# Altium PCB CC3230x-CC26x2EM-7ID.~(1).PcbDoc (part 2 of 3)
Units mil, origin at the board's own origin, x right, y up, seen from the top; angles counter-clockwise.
Board outline 2700 x 2300 mil, 4 copper layers (Top Layer, GND, PWR, Bottom Layer), stack 48.84 mil thick; 159 components, 102 nets, 511 pads, 818 vias.
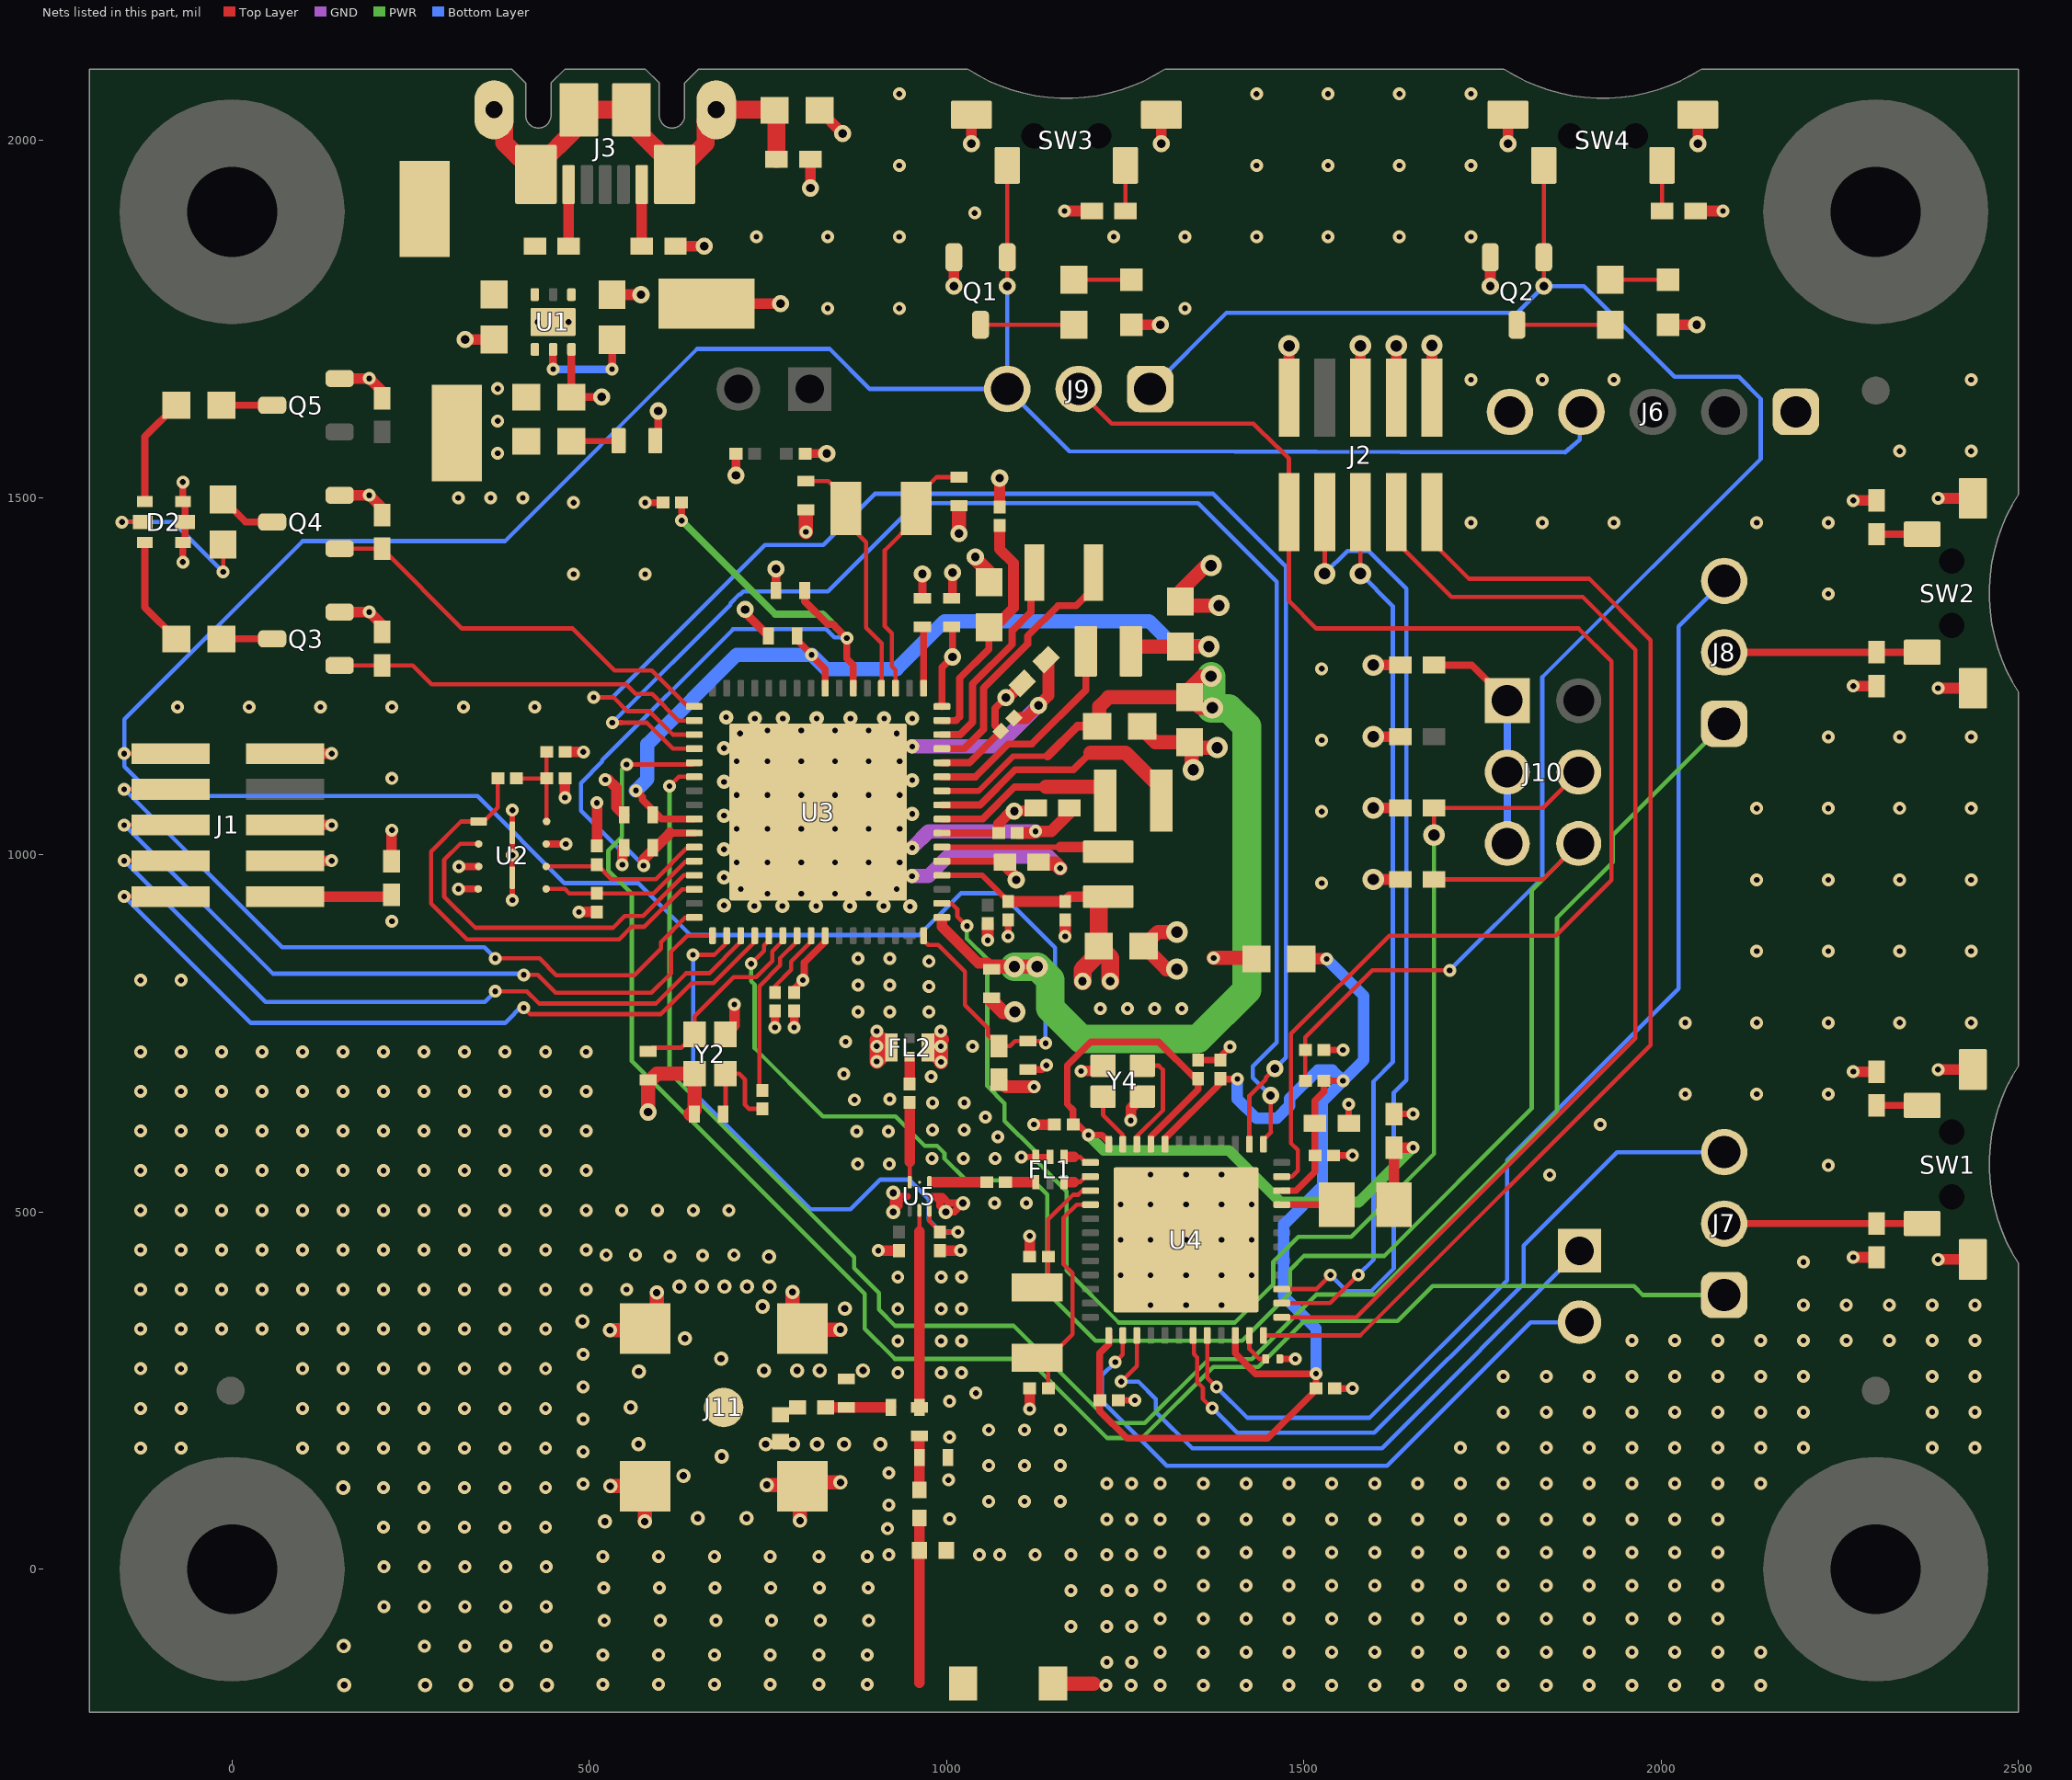
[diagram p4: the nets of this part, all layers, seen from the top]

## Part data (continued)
R14 R15: "RES, 100, 1%, 0.1 W, 0402", Alternate Manufacturer=YAGEO, Alternate PartNumber=RC0402FR-07100RL, Manufacturer=Panasonic, PartNumber=ERJ-2RKF1000X, Power_W=100mW, Supplier Part Number 1=P100LCT-ND, TempCo="100 ppm/C", Tolerance_%=1%, Value2=0.1W, Value_Code=100R, ValueDisplayed=100
R16 R17 R18: "RES, 100 k, 5%, 0.063 W, AEC-Q200 Grade 0, 0402", Alternate Manufacturer=YAGEO, Alternate PartNumber=RC0402JR-07100KL, Manufacturer=Vishay-Dale, PartNumber=CRCW0402100KJNED, Power_W=63mW, Supplier Part Number 1=541-100KJCT-ND, TempCo="200 ppm/C", Tolerance_%=5%, Value2=0.063W, Value_Code=100k
R19 R21 R27 R28: library part CMP-0027008-4, "RES, 0, 5%, 0.05 W, 0201", Manufacturer=Vishay-Dale, Power_W=50mW, Supplier Part Number 1=72M6743, TempCo=ppm/C, Tolerance_%=5%, Value2=0.05W, Value_Code=0000, ValueDisplayed=0
R20 R30 R31: library part CMP-0026823-3, "RES, 100 k, 5%, 0.063 W, AEC-Q200 Grade 0, 0402", Manufacturer=Vishay-Dale, Power_W=63mW, Supplier Part Number 1=541-100KJCT-ND, TempCo="200 ppm/C", Tolerance_%=5%, Value2=0.063W, Value_Code=100k
R29: library part CMP-0026886-3, "RES, 270, 5%, 0.063 W, AEC-Q200 Grade 0, 0402", Manufacturer=Vishay-Dale, Power_W=63mW, Supplier Part Number 1=541-270JCT-ND, TempCo="200 ppm/C", Tolerance_%=5%, Value2=0.063W, Value_Code=270R, ValueDisplayed=270
R32: library part CMP-0026892-5, "RES, 2.7 k, 5%, 0.063 W, AEC-Q200 Grade 0, 0402", Manufacturer=Vishay-Dale, Power_W=63mW, Supplier Part Number 1=541-2.7KJCT-ND, TempCo="200 ppm/C", Tolerance_%=5%, Value2=0.063W, Value_Code=2k70, ValueDisplayed=2.7k
R33 R34: library part CMP-0027011-3, "RES, 0, 5%, 0.05 W, 0201", Alternate Manufacturer=Vishay-Dale, Alternate PartNumber=CRCW02010000Z0ED, Manufacturer=Panasonic, Power_W=50mW, Supplier Part Number 1=P0.0AGCT-ND, TempCo="600 ppm/C", Tolerance_%=5%, Value2=0.05W, Value_Code=0000, ValueDisplayed=0
SH-J1 SH-J2 SH-J3 SH-J4: library part CMP-0003761-2, "Shunt, 2.54mm, Gold, Black", Manufacturer="Wurth Elektronik", Supplier Part Number 1=732-2678-ND
SW1 SW2 SW3 SW4: "Switch, SPST, 0.05 A, 12 VDC, SMD", Alternate Manufacturer=----, CurrentRating_mA=50A, Manufacturer=Diptronics, PartNumber=1188E-1K2-V-TR
TP1 TP2 TP3: library part CMP-0055152-1, "Test Point, Miniature, SMT", Manufacturer=Keystone, Supplier Part Number 1=36-5015TR-ND
U1: library part CMP-0073832-5, "Single Output LDO, 1A, Adj. (1.2 to 5.0V), Reverse Current Protection, DRV0006A (WSON-6)", Alternate Manufacturer="Texas Instruments", Alternate PartNumber=TPS73733DRVT, Operating Temperature Range="-40 to 125 C", Rating=Catalog
U2: library part CMP-0086651-1, "FLASH - NOR Memory IC 32Mb (4M x 8) SPI 80MHz 8-USON (4x3)", Manufacturer=Macronix
U3: library part CMP-0084310-2, "SimpleLink Wi-Fi, Single-Chip Wireless MCU Solution, RGK0064B (VQFN-64)", Alternate Manufacturer="Texas Instruments"
U4: library part CMP-0083675-2, "SimpleLink(TM) Bluetooth(R) 5 low energy Wireless MCU, RGZ0048A (VQFN-48)", Alternate Manufacturer="Texas Instruments", Alternate PartNumber=CC2642R1FRGZT, Operating Temperature Range="-40 to 85 C", Rating=#N/A
U5: library part CMP-0065464-1, "0.03 GHz-6 GHz SPDT Switch", Alternate Manufacturer=----, Manufacturer=Richwave
Y1: "CRYSTAL, 32.768KHz, 9PF, SMD", Alternate Manufacturer=----, Frequency Stability=+/-20ppm, Frequency_Fixed=32.768kHz, Manufacturer="Abracon Corporation", PartNumber=ABS07-32.768KHZ-9-T, Supplier Part Number 1=535-9544-1-ND
Y2: library part CMP-0077111-2, "Crystal, 40 MHz, 8 pF, SMD", Alternate Manufacturer=----, Alternate PartNumber="Order Directly from TXC", Frequency Stability=±15ppm, Frequency_Fixed=40MHz, Manufacturer="TXC Corporation"
Y3: library part CMP-0079303-1, "Crystal, 32.768 KHz, 20 ppm, 7 pF, SMD", Frequency Stability="20 ppm", Frequency_Fixed=32.768kHz, Load Capacitance="7 pF", Manufacturer=Epson, Supplier Part Number 1=732-FC135-32.76KAAG0
Y4: library part CMP-0088076-1, "48MHz ±20ppm Crystal 7pF 50 Ohms 4-SMD, No Lead", Frequency_Fixed=48MHz, Frequency Tolerance=20ppm, Load Capacitance=7pF, Manufacturer=Kyocera
ZZ1: library part CMP-0003616-3
ZZ2: library part CMP-0077236-1
ZZ3: library part CMP-0077237-1
ZZ4: library part CMP-0077238-1

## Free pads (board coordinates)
  rrect0% 16.73x16.73 smd paste-100 mask-100: 2(948.06,890.22)

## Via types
v1: diameter 18, hole 8, Top Layer to Bottom Layer, tented both sides, 626 vias
v2: diameter 19.68, hole 7.87, Top Layer to Bottom Layer, 55 vias
v3: diameter 20, hole 10, Top Layer to Bottom Layer, tented both sides, 48 vias
v4: diameter 24, hole 12, Top Layer to Bottom Layer, tented both sides, 37 vias
v5: diameter 20, hole 8, Top Layer to Bottom Layer, tented both sides, 24 vias
v6: diameter 30, hole 16, Top Layer to Bottom Layer, tented both sides, 23 vias
v7: diameter 20, hole 8, Top Layer to Bottom Layer, tented bottom, 4 vias
v8: diameter 18, hole 8, Top Layer to Bottom Layer, 1 vias

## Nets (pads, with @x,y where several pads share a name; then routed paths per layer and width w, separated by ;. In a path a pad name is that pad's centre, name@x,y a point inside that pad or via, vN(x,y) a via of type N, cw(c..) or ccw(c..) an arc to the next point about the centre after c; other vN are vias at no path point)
BT_P14_DIO_8: J5.2 U4.14 | length 892.8
  Top Layer w6: v1(1235.85,289.87) 1246.37,300.39 U4.14@1246.37,327.21
  Bottom Layer w6: v1(1235.85,289.87) 1217.27,271.29 1217.27,235.27 1307.69,144.85 1616.09,144.85 1816.99,345.75 J5.2@1885.45,345.75
BT_P15_DIO_9: J5.1 U4.15 | length 878.6
  Top Layer w6: v1(1244.22,262.62) 1266.05,284.45 U4.15@1266.05,327.21
  Bottom Layer w6: v1(1244.22,262.62) 1268.43,262.62 1292.66,238.39 1292.66,220.34 1343.71,169.3 1609,169.3 J5.1@1885.45,445.74
BT_P19_DIO_13: J7.3 U4.19 | length 1037.4
  Top Layer w6: U4.19@1344.79,327.21 1345.93,326.08 1345.93,301.04 1350.6,296.37 1350.6,262.19 1358.47,254.32 1358.47,238.31 1370.92,225.86 v1(1371.57,225.86)
  Bottom Layer w6: v1(1371.57,225.86) 1406.45,190.98 1598.26,190.98 1807.15,399.87 1807.15,452.87 1938.14,583.86 J7.3@2087.92,583.86
BT_P20_DIO_14: J8.3 U4.20 | length 1686.6
  Top Layer w6: U4.20@1364.48,327.21 1364.48,267.94 v1(1377.47,254.94)
  Bottom Layer w6: v1(1377.47,254.94) 1420.38,212.03 1591.64,212.03 1783.98,404.37 1783.98,572.56 2024.34,812.92 2024.34,1319.89 J8.3@2087.92,1383.47
BT_P35_nReset: J2.10 J9.2 U4.35 | length 2087.8
  Top Layer w6: J9.2@1182.22,1652.09 1230.67,1603.64 1429.21,1603.64 1461.5,1571.35 1462.23,1571.35 1478.92,1554.66 1478.92,1355.02 1517.13,1316.8 1884.18,1316.8 1930.14,1270.84 1930.14,964.73 1852.15,886.74 1619.21,886.74 1481.88,749.41 1481.88,596.22 1491.49,586.61 1491.49,558.18 1482.97,549.65 U4.35@1468.81,549.65
BT_RF: FL1.1 R34.2 | length 39.1
  Top Layer w15: R34.2@1082.14,541.78 FL1.1@1121.26,541.78
DCDC_SW: L7.1 U4.33 | length 77.1
  Top Layer w9.45: U4.33@1468.81,510.28 L7.1@1545.87,510.28
DIO_16/JTAG_TDO: J2.6 U4.26 | length 1220.6
  Top Layer w6: U4.26@1468.81,372.49 1536.5,372.49 v1(1575.87,411.86) ; v6(1578.92,1393.54) J2.6@1578.92,1470.38
  Bottom Layer w6: v1(1575.87,411.86) 1597.19,433.18 1597.19,682.87 1624.17,709.85 1624.17,1348.29 v6(1578.92,1393.54)
DIO_17/JTAG_TDI: J2.8 U4.27 | length 1372.8
  Top Layer w6: U4.27@1468.81,392.17 1517.34,392.17 v1(1537.03,411.86) ; v6(1528.92,1393.54) J2.8@1528.92,1470.38
  Bottom Layer w6: v6(1528.92,1393.54) 1560.77,1425.39 1590.6,1425.39 1643.24,1372.75 1643.24,684.82 1625.58,667.15 1625.58,421.19 1593.32,388.93 1559.95,388.93 v1(1537.03,411.86)
GND: C1.2 C2.2 C3.2 C4.2 C5.2 C6.2 C7.2 C8.2 C9.2 C10.2 C11.2 C12.2 C13.2 C14.2 C15.2 C16.2 C17.2 C18.2 C19.2 C20.2 C21.2 C22.2 C23.2 C24.2 C25.2 C26.2 C27.2 C28.2 C29.2 C30.2 C31.2 C32.2 C33.2 C34.2 C35.2 C36.2 C37.2 C38.2 C39.2 C40.2 C41.2 C42.2 C43.2 C44.1 C47.2 C49.2 C50.2 D1.2 E1.1 E1.2 FL1.5 FL1.6 FL2.2 FL2.4 J1.3 J1.5 J1.9 J2.3 J2.5 J2.9 J6.5 J11.2 J11.3 J11.4 J11.5 L2.2 L9.2 L10.1 L10.2 Q1.2 Q2.2 Q3.2 Q4.2 Q5.2 R3.1 R12.2 R13.2 R14.1 R15.1 R16.2 R17.2 R18.2 R23.1 R24.1 R30.1 R31.1 R32.1 R35.1 R36.1 SW1.1 SW1.2 SW2.1 SW2.2 SW3.1 SW3.2 SW4.1 SW4.2 TP3.1 U1.3 U1.7@449.17,1745.82 U2.4 U2.9 U2.10 U3.65@820,1060 U4.49 U5.2 Y2.2 Y2.4 Y4.2 Y4.4 | length 5704.5
  Top Layer w7.87: v1(392.2,936.49) U2.10@392.2,967.99 v1(392.2,999.49) U2.9@392.2,1030.98 v1(392.2,1062.48)
  Top Layer w9: v1(1104.36,577.21) FL1.6@1124.79,577.21 FL1.5@1144.47,577.21
  Top Layer w9.45: C6.2@1113.53,699.34 1133.51,699.34 v1(1139.5,705.33) ; C34.2@1240.12,236.52 v1(1263.22,236.52) ; C40.2@1351.65,712.65 C36.2@1383.14,712.65 1383.14,717.91 v1(1396.55,731.32) ; C44.1@1466.05,294.44 v1(1487.88,294.44) ; C5.2@1527.86,726.94 v1(1554.53,726.94) ; C38.2@1541.24,579.25 v1(1567.91,579.25) ; C35.2@1542.81,253.06 v1(1567.91,253.06) ; C37.2@1562.5,624.2 v1(1562.5,650.88) ; C39.2@1625.87,637.37 v1(1652.54,637.37)
  Top Layer w10: v1(316.8,952.24) U2.4@344.35,952.24 ; U3.65@820,1060 U3.65@860.07,1060 ; 945.03,521.77 939.86,521.77 ; 978.66,521.77 983.84,521.77 ; v1(1085.88,885.78) C19.2@1085.88,908.75 ; 939.86,521.77 933.32,515.22 933.32,508.45 v3(924.96,500.09) v3(924.96,526.81) 930.01,521.77 939.86,521.77 ; 983.84,521.77 990.38,515.22 990.38,508.45 v3(998.73,500.09) 1010.31,500.09 v3(1022.63,512.42) 1003.03,512.42 993.69,521.77 983.84,521.77
  Top Layer w11: U1.3@474.76,1707.43 C2.2@474.76,1640.84 v4(517.33,1640.84) ; D1.2@596.24,1578.75 v4(596.24,1621.32)
  Top Layer w12: v4(717.72,1343.4) 717.72,1339.08 C25.2@750.4,1306.4 ; v1(759.69,758.27) C28.2@759.69,781.27 ; C12.2@761.16,1369.99 v4(761.16,1400.37) ; v1(786.58,758.27) C18.2@786.58,781.27 ; C27.2@966,1362.62 v4(966,1393) ; C16.2@1007,1362.62 1008,1363.62 v4(1008,1395)
  Top Layer w15: 961.85,-158.86 L10.1@961.85,26.39 C49.2@961.85,71.71
  Top Layer w15.01: J1.3@76.64,991.65 v1(139.4,991.65) ; J1.5@76.64,1041.65 v1(139.4,1041.65) ; J1.9@76.64,1141.65 v1(139.4,1141.65) ; Q3.2@150.53,1339.78 v1(192.02,1339.78) 209.96,1321.84 R16.2@209.96,1312.22 ; Q4.2@150.53,1503.24 v1(192.02,1503.24) 209.96,1485.3 R17.2@209.96,1475.68 ; Q5.2@150.53,1666.7 v1(192.02,1666.7) 209.96,1648.77 R18.2@209.96,1639.14 ; v4(326.15,1721.21) C1.2@366.53,1721.21 ; v1(465.71,1080.03) 465.71,1106.71 C14.2@466.02,1107.03 ; v1(485.12,920.02) R24.1@510.53,920.02 ; R23.1@510.53,1012.27 v1(510.53,1072.76) ; v1(522.24,1105.16) 526.39,1105.16 537.67,1093.87 537.67,1066.95 C24.2@548.62,1056 ; C3.2@531.79,1784.02 v4(572.17,1784.02) ; v1(545.98,986.3) 545.98,1007.35 C13.2@548.62,1010 ; L2.2@620.43,1851.8 v4(660.81,1851.8) ; TP3.1@663.85,1771.57 v4(767.47,1771.57) ; Y2.4@690.51,748.7 702.91,761.1 v1(702.91,790.38) ; v4(809.12,1933.42) C4.2@809.12,1973.8 ; R3.1@821.99,2042.15 v4(854.35,2009.79) ; v1(904.21,446) R35.1@933.07,446 ; R36.1@990.63,446 v1(1019.49,446) ; v4(1009.88,1796.05) Q1.2@1009.88,1836.43 ; v4(1034.48,1995.5) SW3.2@1034.48,2035.88 ; v1(1116.13,224.42) C42.2@1116.13,253.28 ; C43.2@1116.13,437.63 v1(1116.13,466.49) ; v1(1121.98,622.46) C41.2@1150.84,622.46 ; v1(1164.76,1901.11) R14.1@1202.79,1901.11 ; v1(1188.01,697.41) 1210.99,697.41 Y4.4@1218.79,705.21 ; v1(1257.6,628.19) 1257.6,645.32 Y4.2@1273.91,661.63 ; v4(1300.23,1995.5) SW3.1@1300.23,2035.88 ; J2.9@1478.92,1635.73 v6(1478.92,1712.57) ; J2.5@1578.92,1635.73 v6(1578.92,1712.57) ; v6(1596.89,965.54) R32.1@1634.7,965.54 ; v6(1596.89,1065.54) R31.1@1634.7,1065.54 ; v6(1596.89,1165.54) R30.1@1634.7,1165.54 ; J2.3@1628.92,1635.73 v6(1628.92,1712.57) ; v4(1760.67,1796.05) Q2.2@1760.67,1836.43 ; v4(1785.27,1995.5) SW4.2@1785.27,2035.88 ; R15.1@2048.07,1901.11 v1(2086.1,1901.11) ; v4(2051.02,1995.5) SW4.1@2051.02,2035.88 ; v1(2268.67,436.62) R12.2@2301.1,436.62 ; v1(2268.67,1236.22) R13.2@2301.1,1236.22 ; v1(2387.18,433.66) SW1.1@2435.87,433.66 ; v1(2387.18,699.41) SW1.2@2435.87,699.41 ; v1(2387.18,1233.27) SW2.1@2435.87,1233.27 ; v1(2387.18,1499.02) SW2.2@2435.87,1499.02
  Top Layer w16.54: v1(1057.24,880.39) C32.2@1057.24,903.75 ; C11.2@1094.06,1191.37 1110.61,1191.37 v4(1128.37,1209.13) 1142.19,1222.96 1142.19,1270.24 C10.2@1139.03,1273.41 ; C9.2@1098.78,1030.47 1121.97,1030.47 v1(1124.35,1032.86) 1146.24,1032.86 1171.54,1058.15 C8.2@1171.54,1065.69 ; v1(1165.68,885.78) C17.2@1165.68,908.75
  Top Layer w17.72: 911.35,719.33 FL2.4@922.48,730.46 911.35,741.59 ; 984.79,719.33 FL2.2@973.66,730.46 984.79,741.59
  Top Layer w19.9: v4(582.17,639.98) 582.17,681.38 594.37,693.58 Y2.2@647.2,693.58 ; C31.2@641.38,637 647.2,642.83 Y2.2@647.2,693.58 ; Y2.2@646.89,693.27 Y2.2@647.2,693.58 ; v1(802.97,1451.95) C29.2@802.97,1479.33 ; v4(1016.97,1449.62) C30.2@1016.97,1485 ; v4(1040,1417) 1040,1414.43 1059,1395.43 C26.2@1059,1381.5 ; C7.2@1128.62,989.5 1130.29,987.83 1152.22,987.83 v1(1158.78,981.27) ; E1.2@1148.7,-160 1205.9,-160 ; v6(1322,840) 1307.5,840 C15.2@1275.5,872 1295.5,892 v6(1322,892) ; C21.2@1343,1154.5 1343,1121 v6(1345,1119) ; v6(1370,1405) 1363,1405 1327,1369 C23.2@1327,1354.5 1332.5,1349 v6(1381,1349)
  Top Layer w20: v3(528.72,334.74) 575.81,334.74 594.13,353.06 594.08,353.11 v3(594.08,387.25) ; v3(529.14,116.34) 575.59,116.34 576.55,117.3 J11.3@577.7,116.16 577.25,115.71 577.38,115.59 v3(577.38,66.73) ; v3(748.01,117.96) 796.36,117.96 J11.4@798.17,116.16 ; v3(784.08,387.98) 784.08,351.26 783.81,350.99 J11.5@798.17,336.63 799.62,335.18 799.97,335.53 v3(851.02,335.53) ; v3(794.63,67.96) 794.63,112.62 J11.4@798.17,116.16 ; J11.4@803.84,121.59 803.72,121.71 J11.4@798.17,116.16 ; J11.4@807.37,121.45 v3(851.33,121.45) ; v1@901.95,740.68 v1(901.95,732.2) ; 911.35,719.33 902.72,710.7 v1(901.95,710.7) v1(901.95,732.2) ; 911.35,741.59 v1(901.95,732.2) ; 984.79,719.33 v1@992.03,712.09 ; 984.79,741.59 993.28,741.59 990.38,738.7 992.03,737.05 v1@992.03,712.09 ; v1(992.03,710.11) v1@992.03,712.09 ; C22.2@1062.64,796.17 1078.6,780.21 v6(1095.31,780.21) ; C20.2@1273.5,1180 1273.5,1176 1291.99,1157.5 C21.2@1334,1157.5 ; v6(1378.43,1150.19) 1347.31,1150.19 1343,1154.5 C21.2@1342.5,1155 ; C21.2@1334,1157.5 1337.5,1154 1338.5,1155 C21.2@1342.5,1155 ; C21.2@1334,1157.5 C21.2@1340,1157.5 C21.2@1342.5,1155
  GND w19.9: v5(951.49,970.12) 974.12,970.12 1001.6,997.6 1142.45,997.6 v1(1158.78,981.27) ; v5(951.7,1009.9) 974.66,1032.86 v1(1124.35,1032.86) ; v5(951.7,1151.63) 1070.87,1151.63 v4(1128.37,1209.13)
  other v1: 1222.89,-162.35 1257.89,-162.35 1298.9,-162.35 1358.9,-162.35 1418.9,-162.35 1478.9,-162.35 1538.9,-162.35 1598.9,-162.35 1658.9,-162.35 1718.9,-162.35 1778.9,-162.35 1838.9,-162.35 1898.9,-162.35 1958.9,-162.35 2018.9,-162.35 2078.9,-162.35 2138.9,-162.35 518.9,-161 596.9,-161 674.9,-161 752.9,-161 820.9,-161 888.9,-161 1223.9,-130 1258.9,-130 518.9,-120 596.9,-120 674.9,-120 752.9,-120 820.9,-120 888.9,-120 1298.9,-115.88 1358.9,-115.88 1418.9,-115.88 1478.9,-115.88 1538.9,-115.88 1598.9,-115.88 1658.9,-115.88 1718.9,-115.88 1778.9,-115.88 1838.9,-115.88 1898.9,-115.88 1958.9,-115.88 2018.9,-115.88 2078.9,-115.88 2138.9,-115.88 269.31,-107.63 325.99,-107.63 382.67,-107.63 439.36,-107.63 1173.9,-80 1223.9,-80 1258.9,-80 520.9,-72 598.9,-72 676.9,-72 754.9,-72 822.9,-72 890.9,-72 1298.9,-69.41 1358.9,-69.41 1418.9,-69.41 1478.9,-69.41 1538.9,-69.41 1598.9,-69.41 1658.9,-69.41 1718.9,-69.41 1778.9,-69.41 1838.9,-69.41 1898.9,-69.41 1958.9,-69.41 2018.9,-69.41 2078.9,-69.41 212.62,-52.16 269.31,-52.16 325.99,-52.16 382.67,-52.16 439.36,-52.16 1173.9,-30 1223.9,-30 1258.9,-30 519.9,-26 597.9,-26 675.9,-26 753.9,-26 821.9,-26 889.9,-26 1298.9,-22.94 1358.9,-22.94 1418.9,-22.94 1478.9,-22.94 1538.9,-22.94 1598.9,-22.94 1658.9,-22.94 1718.9,-22.94 1778.9,-22.94 1838.9,-22.94 1898.9,-22.94 1958.9,-22.94 2018.9,-22.94 2078.9,-22.94 212.62,3.31 269.31,3.31 325.99,3.31 382.67,3.31 439.36,3.31 518.9,18 596.9,18 674.9,18 752.9,18 820.9,18 888.9,18 918.9,20 1045.9,20 1073.9,20 1123.9,20 1173.9,20 1223.9,20 1258.9,20 1298.9,23.53 1358.9,23.53 1418.9,23.53 1478.9,23.53 1538.9,23.53 1598.9,23.53 1658.9,23.53 1718.9,23.53 1778.9,23.53 1838.9,23.53 1898.9,23.53 1958.9,23.53 2018.9,23.53 2078.9,23.53 917.28,56.67 211.9,58.77 268.58,58.77 325.27,58.77 381.95,58.77 438.63,58.77 1223.9,70 1258.9,70 1298.9,70 1358.9,70 1418.9,70 1478.9,70 1538.9,70 1598.9,70 1658.9,70 1718.9,70 1778.9,70 1838.9,70 1898.9,70 1958.9,70 2018.9,70 2078.9,70 1004.22,70.54 918.9,90 1058.9,95 1108.9,95 1158.9,95 211.9,114.24 268.58,114.24 325.27,114.24 381.95,114.24 438.63,114.24 491.34,119.39 1223.9,120 1258.9,120 1298.9,120 1358.9,120 1418.9,120 1478.9,120 1538.9,120 1598.9,120 1658.9,120 1718.9,120 1778.9,120 1838.9,120 1898.9,120 1958.9,120 2018.9,120 2078.9,120 2138.9,120 1002.36,124.95 918.9,135 1058.9,145 1108.9,145 1158.9,145 491.34,164.74 -128.2,169.71 -71.52,169.71 98.53,169.71 155.22,169.71 211.9,169.71 268.58,169.71 325.27,169.71 381.95,169.71 438.63,169.71 1718.9,170 1778.9,170 1838.9,170 1898.9,170 1958.9,170 2018.9,170 2078.9,170 2138.9,170 2198.9,170 2378.9,170 2438.9,170 1003.9,185 1058.9,195 1108.9,195 1158.9,195 491.34,210.08 1778.9,220 1838.9,220 1898.9,220 1958.9,220 2018.9,220 2078.9,220 2138.9,220 2198.9,220 2378.9,220 2438.9,220 -128.2,225.17 -71.52,225.17 98.53,225.17 155.22,225.17 211.9,225.17 268.58,225.17 325.27,225.17 381.95,225.17 438.63,225.17 1003.9,235 1040.82,246.51 491.34,255.43 1778.9,270 1838.9,270 1898.9,270 1958.9,270 2018.9,270 2078.9,270 2138.9,270 2198.9,270 2378.9,270 2438.9,270 931.53,274.95 992.08,274.95 1020.76,274.95 -128.2,280.64 -71.52,280.64 98.53,280.64 155.22,280.64 211.9,280.64 268.58,280.64 325.27,280.64 381.95,280.64 438.63,280.64 491.34,300.78 931.53,319.6 992.08,319.6 1020.76,319.6 1958.9,320 2018.9,320 2078.9,320 2138.9,320 2198.9,320 2258.9,320 2318.9,320 2378.9,320 2438.9,320 -128.2,336.11 -71.52,336.11 -14.83,336.11 41.85,336.11 98.53,336.11 155.22,336.11 211.9,336.11 268.58,336.11 325.27,336.11 381.95,336.11 438.63,336.11 931.53,364.26 992.08,364.26 1020.76,364.26 2198.9,370 2258.9,370 2318.9,370 2378.9,370 2438.9,370 -128.2,391.57 -71.52,391.57 -14.83,391.57 41.85,391.57 98.53,391.57 155.22,391.57 211.9,391.57 268.58,391.57 325.27,391.57 381.95,391.57 438.63,391.57 495.32,391.57 552,391.57 931.53,408.91 992.08,408.91 1020.76,408.91 2198.9,430 612.44,438.06 658.44,439.06 523.44,440.06 564.44,440.06 702.44,440.06 -128.2,447.04 -71.52,447.04 -14.83,447.04 41.85,447.04 98.53,447.04 155.22,447.04 211.9,447.04 268.58,447.04 325.27,447.04 381.95,447.04 438.63,447.04 495.32,447.04 -128.2,502.51 -71.52,502.51 -14.83,502.51 41.85,502.51 98.53,502.51 155.22,502.51 211.9,502.51 268.58,502.51 325.27,502.51 381.95,502.51 438.63,502.51 495.32,502.51 545.32,502.51 595.32,502.51 645.32,502.51 695.32,502.51 1066.93,512.42 1111.23,512.42 1843.96,552 -128.2,557.98 -71.52,557.98 -14.83,557.98 41.85,557.98 98.53,557.98 155.22,557.98 211.9,557.98 268.58,557.98 325.27,557.98 381.95,557.98 438.63,557.97 495.32,557.97 2233.55,565.06 875.52,566.95 919.82,566.95 979.25,575.25 1023.54,575.25 1067.84,575.25 1071.33,605.31 -128.2,613.44 -71.52,613.44 -14.83,613.44 41.85,613.44 98.53,613.44 155.22,613.44 211.9,613.44 268.58,613.44 325.27,613.44 381.95,613.44 438.63,613.44 495.32,613.44 873.98,612.77 918.28,612.77 979.94,615.16 1024.23,615.16 1914.67,622.71 1054.22,632.74 980.29,653.04 1024.58,653.04 871.04,657.01 920.25,658.07 2033.55,665.06 2133.55,665.06 2233.55,665.06 -128.2,668.91 -71.52,668.91 -14.83,668.91 41.85,668.91 98.53,668.91 155.22,668.91 211.9,668.91 268.58,668.91 325.27,668.91 381.95,668.91 438.63,668.91 495.32,668.91 978.34,689.49 855.82,693.19 -128.2,724.38 -71.52,724.38 -14.83,724.38 41.85,724.38 98.53,724.38 155.22,724.38 211.9,724.38 268.58,724.38 325.27,724.38 381.95,724.38 438.63,724.38 495.32,724.38 991.79,732.07 1036.09,732.07 858.47,738.41 901.95,753.09 991.64,753.38 2033.55,765.06 2133.55,765.06 2233.55,765.06 2333.55,765.06 2433.55,765.06 875.93,780.27 920.23,780.27 975.27,780.4 1215.13,784.78 1253,784.78 1290.87,784.78 1328.73,784.78 975.27,815.62 875.93,817.53 920.23,817.53 -128.2,824.38 -71.52,824.38 975.27,850.84 875.93,854.78 920.23,854.78 2133.55,865.06 2233.55,865.06 2333.55,865.06 2433.55,865.06 223.69,906.85 1524.79,960.5 2133.55,965.06 2233.55,965.06 2333.55,965.06 2433.55,965.06 1524.79,1060.5 2133.55,1065.06 2233.55,1065.06 2333.55,1065.06 2433.55,1065.06 223.69,1106.85 1524.79,1160.5 2233.55,1165.06 2333.55,1165.06 2433.55,1165.06 -76.31,1206.85 23.69,1206.85 123.69,1206.85 223.69,1206.85 323.69,1206.85 423.69,1206.85 1524.79,1260.5 2233.55,1365.06 477.87,1392.99 577.87,1392.99 1733.55,1465.06 1833.55,1465.06 1933.55,1465.06 2133.55,1465.06 2233.55,1465.06 477.87,1492.99 2333.55,1565.06 2433.55,1565.06 1733.55,1665.06 1833.55,1665.06 1933.55,1665.06 2433.55,1665.06 833.55,1765.06 933.55,1765.06 1333.55,1765.06 733.55,1865.06 833.55,1865.06 933.55,1865.06 1233.55,1865.06 1333.55,1865.06 1433.55,1865.06 1533.55,1865.06 1633.55,1865.06 1733.55,1865.06 1039.08,1898.33 933.55,1965.06 1433.55,1965.06 1533.55,1965.06 1633.55,1965.06 1733.55,1965.06 933.55,2065.06 1433.55,2065.06 1533.55,2065.06 1633.55,2065.06 1733.75,2065.34
  other v2: 1285.34,369.53 1334.95,369.53 1384.56,369.53 1243.41,411.46 1285.34,411.46 1334.95,411.46 1384.56,411.46 1426.48,411.46 1243.41,461.07 1285.34,461.07 1334.95,461.07 1384.56,461.07 1426.48,461.07 1243.41,510.67 1285.34,510.67 1334.95,510.67 1384.56,510.67 1426.48,510.67 1285.34,552.6 1334.95,552.6 1384.56,552.6 749.13,945.83 796.38,945.83 843.62,945.83 890.87,945.83 705.83,989.13 749.13,989.13 796.38,989.13 843.62,989.13 890.87,989.13 934.17,989.13 705.83,1036.38 749.13,1036.38 796.38,1036.38 843.62,1036.38 890.87,1036.38 934.17,1036.38 705.83,1083.62 749.13,1083.62 796.38,1083.62 843.62,1083.62 890.87,1083.62 934.17,1083.62 705.83,1130.87 749.13,1130.87 796.38,1130.87 843.62,1130.87 890.87,1130.87 934.17,1130.87 749.13,1174.17 796.38,1174.17 843.62,1174.17 890.87,1174.17 427.51,1745.82 470.82,1745.82
  other v3: 156.94,-162.1 270.31,-162.1 326.99,-162.1 383.67,-162.1 440.36,-162.1 155.94,-107.63 521.64,66.73 651.61,71.66 719.89,71.66 155.22,114.24 631.41,130.9 685.23,158 568.55,174.93 746.6,175 784.51,175 818.61,175 856.46,175 907.13,175 557.73,226.7 568.98,276.85 744.16,278.29 790.71,278.29 822.42,278.29 882.9,278.29 684.24,294.62 633.56,323.19 490.34,347.12 857.25,364.75 742.11,367.78 625.74,395.54 657.35,395.54 688.97,395.54 720.58,395.54 752.2,395.54 751.18,437.32
  other v5: 730.66,928.3 769.9,928.3 817.14,928.3 864.39,928.3 911.63,928.3 948.67,927.77 688.3,929.12 688.3,968.37 688.3,1007.61 688.3,1054.86 951.7,1057.14 688.3,1102.1 951.7,1104.39 688.3,1149.34 731.48,1190.88 770.72,1190.88 817.97,1190.88 865.21,1190.88 912.46,1190.88 951.7,1190.88 691.25,1192.67
  other v7: 711.89,951.89 929.9,951.89 710.9,1169.9 929.9,1169.9
NetC3_1: C3.1 U1.2 | length 151.8
  Top Layer w11: v1(449.17,1679.66) U1.2@449.17,1707.43 ; v1(531.79,1679.66) C3.1@531.79,1721.03
  Bottom Layer w11: v1(449.17,1679.66) v1(531.79,1679.66)
NetC4_1: C4.1 J3.6 J3.7 J3.8 J3.9 J3.10 J3.11 R3.2 | length 685.6
  Top Layer w25: J3.10@366.49,2042.91 380.91,2028.5 380.91,1996.51 J3.11@425.05,1952.36 425.05,1960.63 485.09,2020.67 J3.9@485.09,2042.91 J3.8@558.91,2042.91 558.91,2022.34 618.95,1962.3 J3.6@618.95,1952.36 662.55,1995.96 662.55,2027.95 J3.7@677.51,2042.91 758.24,2042.91 R3.2@759,2042.15 761.88,2039.28 C4.1@761.88,1973.8
NetC5_1: C5.1 J9.1 Q2.1 R8.1 SW4.4 | length 2430.2
  Top Layer w6: R8.1@1501.88,683.63 C5.1@1501.88,726.94 1501.88,744.55 1595.64,838.32 v1(1703.73,838.32) ; v4(1835.47,1796.05) Q2.1@1835.47,1836.43 SW4.4@1835.47,1965.02
  Bottom Layer w6: J9.1@1284.68,1652.09 1391.34,1758.75 1798.17,1758.75 v4(1835.47,1796.05) 1891.61,1796.05 2018.51,1669.14 2108.29,1669.14 2138.99,1638.44 2138.99,1554.29 1833.38,1248.67 1833.38,967.97 v1(1703.73,838.32)
NetC12_1: C12.1 C13.1 R19.1 U3.10 U3.54 | length 1215
  Top Layer w10: 612.71,1030.47 U3.10@646.77,1030.47 ; v1(628.99,1467.85) R19.1@628.99,1492.99 ; C12.1@801.16,1369.99 801.16,1354.87 833.19,1322.84 840.59,1322.84 v1(860.22,1303.21) 860.22,1274.67 869.21,1265.68 U3.54@869.21,1233.23
  Top Layer w15.01: v1(575.81,984.99) 575.81,993.57 588.62,1006.38 C13.1@588.62,1010 592.24,1010 612.71,1030.47
  PWR w10: v1(628.99,1467.85) 759.84,1337 826.43,1337 v1(860.22,1303.21)
  Bottom Layer w6: v1(575.81,984.99) 555.24,1005.56 544.44,1005.56 488,1062.01 488,1100.55 517.99,1130.55 517.99,1132.3 700.71,1315.01 ; 700.71,1316.01 831,1316.01 842.78,1304.22 v1@859.21,1304.22
NetC14_1: C14.1 R21.1 R22.2 U2.8 | length 139.6
  Top Layer w6: R22.2@397.78,1107.03 C14.1@440.04,1107.03 ; U2.8@440.04,1046.73 C14.1@440.04,1107.03 ; R21.1@440.04,1144.04 C14.1@440.04,1107.03
NetC26_1: C26.1 R27.1 U3.47 | length 338.5
  Top Layer w10: U3.47@993.23,1187.95 1012.95,1187.95 1017.98,1192.98 1017.98,1246.98 1059,1288 C26.1@1059,1318.5
  Top Layer w15.01: C26.1@1059,1318.5 1066.5,1318.5 1093.35,1345.35 1093.35,1408.65 1074,1428 R27.1@1073.99,1461.03
NetC27_1: C27.1 U3.49 | length 86.5
  Top Layer w10: C27.1@966,1319 967.64,1317.36 U3.49@967.64,1233.23
NetC28_1: C28.1 U3.24 | length 91.9
  Top Layer w6: C28.1@759.69,807.25 759.69,816.24 782.42,838.97 782.42,850.52 U3.24@810.16,878.26
NetC29_1: C29.1 U3.52 Y1.2 | length 352.2
  Top Layer w6: C29.1@803,1522.95 834.47,1522.95 858.79,1498.64 Y1.2@858.79,1485 858.79,1466.21 887.3,1437.7 887.3,1388.32 887.3,1317.93 909,1296.22 909,1233.62 U3.52@908.58,1233.23
NetC30_1: C30.1 U3.51 Y1.1 | length 362.9
  Top Layer w6: U3.51@928.27,1233.23 928.27,1258.7 922.97,1264 922.97,1310.03 913.28,1319.73 913.28,1426.31 957.19,1470.21 957.19,1500.21 985.59,1528.62 C30.1@1016.97,1528.62
NetC31_1: C31.1 R28.1 Y2.3 | length 150.8
  Top Layer w6: C31.1@686.89,637 690.51,640.62 Y2.3@690.51,693.58 709.61,693.58 717.66,685.53 717.66,650.15 723.4,644.41 R28.1@742.12,644.41
NetC33_1: C33.1 U3.22 Y2.1 | length 282.3
  Top Layer w6: C33.1@582.17,725 587.17,730 628.5,730 Y2.1@647.2,748.7 647.2,774.13 702.06,828.99 733.14,828.99 755.76,851.61 755.76,864.97 770.79,880 U3.22@770.79,886.77
NetC42_1: C42.1 U4.4 Y3.1 | length 326
  Top Layer w6: C42.1@1142.11,253.28 1142.11,280.65 Y3.1@1126.51,296.24 1143.4,296.24 1176.03,328.88 1176.03,414.41 1163.52,426.93 1163.52,492.09 1181.7,510.28 U4.4@1201.09,510.28
NetC43_1: C43.1 U4.3 Y3.2 | length 177.1
  Top Layer w6: Y3.2@1126.51,394.67 1142.11,410.27 C43.1@1142.11,437.63 1142.11,489.59 1176.68,524.16 1184.05,524.16 1189.86,529.97 U4.3@1201.09,529.97
NetC44_2: C44.2 U4.23 | length 47.5
  Top Layer w6: U4.23@1423.53,327.21 1423.53,308.32 1437.41,294.44 C44.2@1446.37,294.44
NetC45_1: C45.1 C48.1 U5.5 | length 275.9
  Top Layer w6: 961.85,472.66 U5.5@961.85,502.41
  Top Layer w15: C48.1@961.85,226.53 961.85,472.66
NetC45_2: C45.2 C46.1 C47.1 | length 90.3
  Top Layer w15: C46.1@830.69,226.4 C45.2@920.83,226.4 ; C45.2@921.71,226.4 C45.2@921.85,226.53
NetC46_2: C46.2 J11.1 L9.1
NetC48_2: C48.2 C49.1 C50.1 | length 73.1
  Top Layer w15: C49.1@961.85,111.08 C50.1@961.85,156.39 C48.2@961.85,184.18
NetD1_1: D1.1 R2.2 | length 66.1
  Top Layer w9: R2.2@474.76,1578.75 D1.1@540.87,1579.57
NetD2_2: D2.2 R11.2 | length 153.1
  Top Layer w10: D2.2@-122.1,1494.38 -122.1,1585.33 R11.2@-78.13,1629.3
NetD2_4: D2.4 R10.2 | length 237.7
  Top Layer w6: v1(-154.04,1465.84) D2.4@-125.05,1465.84 ; v1(-12.58,1395.99) R10.2@-12.58,1434.34
  Bottom Layer w6: v1(-154.04,1465.84) -82.43,1465.84 v1(-12.58,1395.99)
NetD2_6: D2.6 R9.2 | length 153.1
  Top Layer w10: D2.6@-122.1,1437.29 -122.1,1346.35 R9.2@-78.13,1302.37
NetD3_1: D3.1 R6.2 | length 80.4
  Top Layer w6: R6.2@1177.99,1804.93 D3.1@1258.42,1804.93
NetD4_1: D4.1 R7.2 | length 80.4
  Top Layer w6: R7.2@1928.77,1804.93 D4.1@2009.21,1804.93
NetFL1_3: FL1.3 U4.2 | length 37.1
  Top Layer w6: 1177.81,541.78 1186.63,541.78 1194.5,549.65 U4.2@1201.09,549.65
  Top Layer w15: FL1.3@1167.27,541.78 1177.81,541.78
NetFL1_4: FL1.4 U4.1 | length 37.1
  Top Layer w6: 1177.81,577.21 1186.63,577.21 1194.5,569.34 U4.1@1201.09,569.34
  Top Layer w15: FL1.4@1167.27,577.21 1177.81,577.21
NetFL2_3: FL2.3 R33.2 | length 37.2
  Top Layer w15: R33.2@948.07,679.36 FL2.3@948.07,716.6
NetJ1_1: J1.1 R1.2 | length 145.7
  Top Layer w15.01: J1.1@76.64,941.65 R1.2@222.3,941.42
NetJ3_1: J3.1 L1.1 | length 86.4
  Top Layer w15.01: L1.1@470.82,1851.8 J3.1@470.82,1938.19
NetJ3_5: J3.5 L2.1 | length 86.4
  Top Layer w15.01: L2.1@573.18,1851.8 J3.5@573.18,1938.19
NetJ7_2: J7.2 R12.1 SW1.3 | length 490.3
  Top Layer w10: SW1.3@2365.01,483.86 R12.1@2301.1,483.86 ; R12.1@2301.1,483.86 J7.2@2087.92,483.86 R12.1@2301.1,483.86
NetJ8_2: J8.2 R13.1 SW2.3 | length 277.1
  Top Layer w10: J8.2@2087.92,1283.47 R13.1@2301.1,1283.47 SW2.3@2365.01,1283.47
NetJ10_1: J10.1 J10.3 J10.5 R29.1 | length 323
  Top Layer w10: R29.1@1681.95,1265.54 1734.61,1265.54 J10.1@1784.35,1215.81
  Bottom Layer w10: J10.5@1784.35,1015.81 J10.3@1784.35,1115.81 J10.1@1784.35,1215.81
NetL3_2: L3.2 U3.38 | length 235.4
  Top Layer w8: U3.38@993.23,1010.79 1159.41,1010.79
  Top Layer w15.01: 1159.41,1010.79 1219.58,1010.79 L3.2@1226,1004.37
NetL4_1: L4.1 U3.41 | length 374.9
  Top Layer w10: U3.41@993.23,1069.84 1046.62,1069.84 1095.78,1119 1176.99,1119 1200.99,1143
  Top Layer w20: 1200.99,1143 1250,1143 1300.37,1092.63 L4.1@1300.37,1076
NetL4_2: L4.2 U3.40 | length 268
  Top Layer w10: U3.40@993.23,1050.16 1050.29,1050.16 1095.13,1095 1138.8,1095
  Top Layer w20: 1138.8,1095 1216.63,1095 L4.2@1216.63,1081 ; L4.2@1216.63,1076 L4.2@1216.63,1081 ; L4.2@1221.63,1076 L4.2@1216.63,1081
NetL5_2: L5.2 U3.43 | length 306.1
  Top Layer w10: U3.43@993.23,1109.21 1040.21,1109.21 1086,1155 1119,1155 1194.63,1230.63 L5.2@1194.63,1285
NetL6_1: L6.1 U3.46 | length 295.3
  Top Layer w10: U3.46@993.23,1168.27 1018.72,1168.27 1036.08,1185.63 1036.08,1239.14 1091.6,1294.66 1091.6,1313.65 1117.66,1339.71 1117.66,1390 L6.1@1122.66,1395
NetL6_2: L6.2 U3.45 | length 367.4
  Top Layer w10: U3.45@993.23,1148.58 1024.49,1148.58 1051.53,1175.62 1051.53,1233.37 1113.19,1295.04 1113.19,1306.06 1155.96,1348.83 1181.21,1348.83 1205.34,1372.95 L6.2@1205.34,1395
NetQ1_3: Q1.3 R6.1 | length 130.7
  Top Layer w6: Q1.3@1047.28,1741.94 R6.1@1177.99,1741.94
NetQ2_3: Q2.3 R7.1 | length 130.7
  Top Layer w6: Q2.3@1798.07,1741.94 R7.1@1928.77,1741.94
NetQ3_3: Q3.3 R9.1 | length 71.2
  Top Layer w10: R9.1@-15.13,1302.37 Q3.3@56.05,1302.37
NetQ4_3: Q4.3 R10.1 | length 81.7
  Top Layer w10: R10.1@-12.58,1497.33 18.92,1465.84 Q4.3@56.05,1465.84
NetQ5_3: Q5.3 R11.1 | length 71.2
  Top Layer w10: R11.1@-15.13,1629.3 Q5.3@56.05,1629.3
NetR4_2: R4.2 SW1.4 | length 63.9
  Top Layer w10: R4.2@2301.1,649.22 SW1.4@2365.01,649.22
NetR5_2: R5.2 SW2.4 | length 63.9
  Top Layer w10: R5.2@2301.1,1448.82 SW2.4@2365.01,1448.82
NetR14_2: R14.2 SW3.3 | length 63.9
  Top Layer w6: R14.2@1250.03,1901.11 SW3.3@1250.03,1965.02
NetR15_2: R15.2 SW4.3 | length 63.9
  Top Layer w6: R15.2@2000.82,1901.11 SW4.3@2000.82,1965.02
NetR28_2: R28.2 U3.23 | length 240.1
  Top Layer w6: R28.2@742.12,670.39 737.7,674.82 737.7,816.17 766.98,845.45 766.98,855.52 790.46,879 U3.23@790.47,886.77
NetR33_1: R33.1 U5.3 | length 111.6
  Top Layer w6: U5.3@948.07,541.78 948.07,570.23
  Top Layer w15: 948.07,570.23 R33.1@948.07,653.38
NetR34_1: R34.1 U5.1 | length 75.8
  Top Layer w15: 980.37,541.78 R34.1@1056.16,541.78
NetU4_46: U4.46 Y4.3 | length 150.3
  Top Layer w6: U4.46@1266.05,594.93 1266.05,605.97 1302.5,642.42 1302.5,699.1 1296.67,704.93 Y4.3@1273.91,704.93
NetU4_47: U4.47 Y4.1 | length 78.1
  Top Layer w6: Y4.1@1218.79,661.63 1218.79,635.82 1246.37,608.25 U4.47@1246.37,594.93
P_24/JTAG_TMS: J2.2 U4.24 | length 1672.3
  Top Layer w6: U4.24@1443.22,327.21 1578.53,327.21 1984.94,733.62 1984.94,1300.71 1899.27,1386.38 1730.8,1386.38 1678.92,1438.26 J2.2@1678.92,1470.38
P_25/JTAG_TCK: J2.4 U4.25 | length 1630.1
  Top Layer w6: U4.25@1468.81,352.8 1573.17,352.8 1963.78,743.41 1963.78,1286.99 1889.98,1360.79 1706.17,1360.79 1628.92,1438.04 J2.4@1628.92,1470.38
SFL_CLK: R23.2 U2.6 U3.11 | length 235.4
  Top Layer w6: U2.6@439.44,983.74 507.98,983.74 R23.2@510.53,986.29 530.83,965.98 592.86,965.98 637.67,1010.79 U3.11@646.77,1010.79
SFL_CS: R22.1 U2.1 U3.14 | length 651.1
  Top Layer w6: R22.1@371.8,1107.03 371.8,1066.05 352.48,1046.73 U2.1@344.95,1046.73 320.57,1046.73 278.31,1004.47 278.31,931.68 328.5,881.5 541.4,881.5 559.25,899.35 577.15,899.35 629.53,951.73 U3.14@646.77,951.73
SFL_DIN: U2.2 U3.13 | length 507.3
  Top Layer w6: U2.2@344.95,1015.23 319.24,1015.23 296.66,992.66 296.66,941.64 340.33,897.97 533.26,897.97 549.56,914.27 575.1,914.27 632.25,971.42 U3.13@646.77,971.42
SFL_DOUT: R24.2 U2.5 U3.12 | length 228.6
  Top Layer w6: U2.5@439.44,952.24 465.51,952.24 471.75,946 R24.2@510.53,946 589.86,946 634.96,991.1 U3.12@646.77,991.1
SOP2: J10.6 R32.2 U3.21 | length 2286.6
  Top Layer w6: v1(726.27,847.58) 744.42,865.73 744.42,873.35 751.1,880.03 U3.21@751.1,886.77 ; R32.2@1681.95,965.54 1834.08,965.54 J10.6@1884.35,1015.81
  PWR w6: v1(726.27,847.58) 726.27,823.14 731.08,818.32 731.08,729.4 826.8,633.68 928.38,633.68 969.2,592.85 986.54,592.85 996.85,582.54 996.85,574.64 1027.25,544.24 1120.72,544.24 1140.65,524.3 1140.65,387.56 1208.43,319.78 1413.62,319.78 1480.59,386.75 1480.59,419.15 1499.98,438.54 1612.24,438.54 1818.48,644.78 1818.48,949.94 J10.6@1884.35,1015.81
VBUS_USB1_5V: C1.1 L1.2 TP1.1 U1.4 U1.6
VCC: C2.1 C7.1 C8.1 C9.1 C10.1 C11.1 D2.1 D2.3 D2.5 D3.2 D4.2 J2.1 J6.1 L8.1 R1.1 R2.1 R4.1 R5.1 R19.2 R20.2 R21.2 R25.2 R26.2 R27.2 R29.2 TP2.1 U1.1 U2.3 U2.7 U3.37 U3.39 U3.44 | length 1199.7
  Top Layer w10: v1(-68.95,1409.85) D2.5@-68.95,1437.29 -66,1440.25 D2.3@-66,1465.84 -66,1491.43 D2.1@-68.95,1494.38 v1(-68.95,1521.82) ; v1(317.4,983.74) U2.3@344.95,983.74 ; U2.7@439.44,1015.23 v1(466.99,1015.23) ; v1(577.87,1492.99) R19.2@603.01,1492.99 ; U3.37@993.23,991.1 1079.78,991.1 C7.1@1081.38,989.5 ; U3.39@993.23,1030.47 C9.1@1072.79,1030.47 ; U3.44@993.23,1128.9 1031.58,1128.9 C11.1@1075.68,1173 1067.52,1181.17 1067.52,1204.91 v4(1082.74,1220.13)
  Top Layer w12: v4(705.01,1531.16) R26.2@705.01,1561.54 ; R25.2@801.68,1561.54 v4(832.05,1561.54)
  Top Layer w15: R1.1@222.99,991 v1@222.99,1033.94
  Top Layer w15.01: R21.2@466.02,1144.04 v1(491.42,1144.04) ; C9.1@1072.79,1030.47 1072.79,1043.72 1090.02,1060.95 v4(1094.56,1060.95) 1095.4,1061.79 1120.39,1061.79 C8.1@1124.29,1065.69 ; R27.2@1073.99,1487.01 v4(1073.99,1527.39) ; C7.1@1081.38,989.5 1081.38,984.49 1097.32,968.55 v4(1097.32,965.01) ; v4(1082.74,1220.13) 1085.75,1220.13 C10.1@1105.62,1240 ; D3.2@1258.42,1741.94 v4(1298.8,1741.94) ; v6(1596.89,1265.54) R29.2@1634.7,1265.54 ; J2.1@1678.92,1636.13 v6(1678.92,1712.96) ; D4.2@2009.21,1741.94 v4(2049.59,1741.94) ; v1(2268.67,696.46) R4.1@2301.1,696.46 ; v1(2268.67,1496.07) R5.1@2301.1,1496.07
  Top Layer w18: R20.2@1073.21,685.21 1083.37,675.05 v1(1122.07,675.05)
  Top Layer w20: v1(1373.54,855.64) 1431.95,855.64 L8.1@1433.24,854.35
  other v1: 223.67,1034.62 316.41,1499.79 361.62,1499.79 406.83,1499.79 371.67,1562.16 371.67,1607.38 371.67,1652.59
VDD_ANA: C15.1 C16.1 C17.1 C18.1 C19.1 L3.1 U3.25 U3.36 U3.48 | length 643.4
  Top Layer w8: U3.36@993.23,971.42 1049.2,971.42 C19.1@1085.88,934.73
  Top Layer w10: C18.1@786.58,807.25 786.58,812.72 v1(798.62,824.76) 800.72,826.86 800.72,849.31 829.84,878.43 U3.25@829.84,886.77 ; U3.48@993.23,1207.64 993.23,1262.23 v4(1008,1277) 1008,1318 C16.1@1007,1319
  Top Layer w15.01: C19.1@1087.1,934.73 C17.1@1165.68,934.73 1172.33,941.38 1212.5,941.38 L3.1@1226,941.38
  Top Layer w25: v4(1190,823) 1190,839.24 1212.5,861.74 C15.1@1212.5,872 1229,855.5 v4(1229,823) ; C15.1@1212.5,877 L3.1@1212.5,941.38
VDD_DIG: C23.1 C24.1 C25.1 L5.1 U3.9 U3.56 | length 1261.8
  Top Layer w10: v1(565,1090) 574.13,1080.87 574.13,1077.11 601.08,1050.16 U3.9@646.77,1050.16 ; C25.1@790.4,1306.4 790.4,1300.6 v1(811,1280) 811,1278.63 829.84,1259.79 U3.56@829.84,1233.23
  Top Layer w19.9: L5.1@1257.62,1285 1264.12,1291.5 C23.1@1327,1291.5 v6(1366.81,1291.5)
  Bottom Layer w19.9: v1(565,1090) 581,1106 581,1155 706,1280 v1(811,1280) 830.95,1260.05 930.05,1260.05 996.98,1326.98 1283.02,1326.98 1318.5,1291.5 v6(1366.81,1291.5)
VDD_PA: C20.1 C21.1 C22.1 U3.33 U3.42 | length 1596.1
  Top Layer w8: U3.42@993.23,1089.53 1044.57,1089.53 1093.04,1138 1141,1138
  Top Layer w12: 1141,1138 1183,1180 C20.1@1210.5,1180
  Top Layer w15.01: U3.33@993.23,909.37 993.23,899.4 1044.19,848.44 1057.62,848.44 C22.1@1062.64,843.41
  Top Layer w19.9: C21.1@1339,1220.5 1339,1232 1357,1250 v6(1370,1250)
  Top Layer w20: C22.1@1062.64,843.41 v6(1094.67,843.41) v6(1126.7,843.41) ; C20.1@1210.5,1180 1213.5,1183 1213.5,1207.5 1226.5,1220.5 C21.1@1339,1220.5 ; C21.1@1340,1220.5 1354.79,1205.7 v6(1371.57,1205.7)
  PWR w40: v6(1094.67,843.41) v6(1126.7,843.41) 1144.71,825.4 1144.71,785.33 1187.99,742.05 1351.46,742.05 1419.91,810.51 1419.91,1179.69 1394.61,1205 1370,1205 1370.7,1205.7 v6(1371.57,1205.7) 1370,1207.27 v6(1370,1250)
  Bottom Layer w20: v6(1094.67,843.41) v6(1126.7,843.41)
VDDR: C39.1 C40.1 C41.1 L7.2 U4.45 U4.48 | length 1117.7
  Top Layer w9: C41.1@1176.83,622.46 1183.41,622.46 v1(1198.24,607.63) 1217.2,607.63 1226.68,598.14 U4.48@1226.68,594.93
  Top Layer w9.45: C41.1@1176.83,622.46 1176.83,642.8 1168.68,650.95 1168.68,705.42 1201.43,738.17 1296.61,738.17 1348.11,686.66 C40.1@1351.65,686.66 1351.65,671.53 1285.74,605.62 U4.45@1285.74,594.93
  Top Layer w15.01: L7.2@1625.87,510.28 C39.1@1625.87,590.13 v1(1652.54,590.13)
  PWR w15: v1(1198.24,607.63) 1219.59,586.27 1395.03,586.27 1467.53,513.77 1576.18,513.77 v1(1652.54,590.13)
VDDS: C34.1 C35.1 C36.1 C37.1 C38.1 L8.2 R8.2 U4.13 U4.22 U4.34 U4.44 | length 1924.2
  Top Layer w9.45: U4.13@1226.68,327.21 1226.68,315.2 1214.14,302.66 C34.1@1214.14,236.52 1214.14,221.37 1252.26,183.24 1449.16,183.24 1516.83,250.91 C35.1@1516.83,253.06 v1(1516.83,273.71) 1432.24,273.71 1403.85,302.11 U4.22@1403.85,327.21 ; U4.44@1305.42,594.93 1305.42,602.81 1383.14,680.53 C36.1@1383.14,686.66 1383.63,686.17 v1(1406.7,686.17) ; U4.34@1468.81,529.97 1488.89,529.97 1515.25,556.32 C38.1@1515.25,579.25 C37.1@1515.25,624.2 1515.25,655.88 1527.86,668.49 R8.2@1527.86,683.63 v1(1554.53,683.63)
  Top Layer w16: L8.2@1496.23,854.35 v1(1531.65,854.35)
  Bottom Layer w16: v1(1406.7,686.17) 1406.7,657.99 1433.43,631.26 1462.05,631.26 1479.63,648.84 1479.63,658.93 1519.34,698.63 1539.53,698.63 v1(1554.53,683.63) ; v1(1516.83,273.71) 1516.83,336.95 1471.62,382.16 1471.62,482.58 1525.76,536.72 1525.76,654.86 v1(1554.53,683.63) ; v1(1531.65,854.35) 1583.58,802.42 1583.58,712.67 v1(1554.53,683.63)
Wi-Fi_nRESET: C6.1 J1.10 J6.4 J9.3 Q1.1 R20.1 SW3.4 U3.32 | length 4669.7
  Top Layer w6: v1(-150.98,1141.65) J1.10@-88.71,1141.65 ; U3.32@967.64,886.77 967.64,880 973.95,873.68 988.26,873.68 1025.38,836.56 1025.38,789.64 1057.79,757.23 1057.79,747.88 R20.1@1073.21,732.45 1088.32,732.45 1095.45,739.57 1134.94,739.57 v1(1138.24,736.27) ; v4(1084.68,1796.05) Q1.1@1084.68,1836.43 SW3.4@1084.68,1965.02
  Bottom Layer w6: v4(1084.68,1796.05) J9.3@1084.68,1652.09 ; v1(1138.24,736.27) 1138.24,779 1151.7,792.45 1151.7,870.05 1075.55,946.2 1019.84,946.2 961.32,887.67 641.51,887.67 568.8,960.38 465.21,960.38 343.23,1082.35 -109.53,1082.35 -150.98,1123.8 v1(-150.98,1141.65) -150.98,1189.6 98.54,1439.11 381.69,1439.11 650.7,1708.13 836.51,1708.13 892.54,1652.09 J9.3@1084.68,1652.09 ; J6.4@1885.79,1617.66 1885.79,1581.13 1865.35,1563.36 1171.73,1565.04 J9.3@1084.68,1652.09
  Bottom Layer w10: J6.4@1885.79,1617.66 J6.4@1888.12,1620
WiFi_P01_GPIO_10: Q4.1 R17.1 U3.1 | length 587.7
  Top Layer w6: Q4.1@150.53,1428.44 R17.1@209.96,1428.44 321.58,1316.81 476.61,1316.81 535.43,1258 587,1258 637.36,1207.64 U3.1@646.77,1207.64
WiFi_P02_GPIO_11: Q3.1 R16.1 U3.2 | length 528.1
  Top Layer w6: Q3.1@150.53,1264.97 R16.1@209.96,1264.97 252.64,1264.97 278.91,1238.7 551.3,1238.7 565,1225 587.68,1225 624.73,1187.95 U3.2@646.77,1187.95
WiFi_P03_GPIO_12: U3.3 U4.38 | length 2121.7
  Top Layer w6: v1(505.71,1220.44) 533.56,1220.44 553,1201 584.1,1201 616.83,1168.27 U3.3@646.77,1168.27 ; U4.38@1423.53,594.93 1423.53,662.56 1446.26,685.29 1446.26,687.98 v4(1459.09,700.8)
  Bottom Layer w6: v1(505.71,1220.44) 532.5,1220.44 745.69,1433.63 827.5,1433.63 899.25,1505.39 1372.85,1505.39 1474.69,1403.54 1474.69,716.41 v4(1459.09,700.8)
WiFi_P04_GPIO_13: U3.4 U4.37 | length 2049.6
  Top Layer w6: 545,1185 580.3,1185 616.72,1148.58 U3.4@646.77,1148.58 ; U4.37@1443.22,594.93 1443.22,601.28 1453.85,611.92 1453.18,612.59 v4(1453.18,663.08)
  Top Layer w8: v1(532,1185) 545,1185
  Bottom Layer w6: v1(532,1185) 697.12,1350.12 697.12,1351.93 709.19,1364 711,1364 715.59,1368.59 833.46,1368.59 957.23,1492.36 1351.64,1492.36 1461.69,1382.31 1461.69,737.54 1428.4,704.25 1428.4,687.86 v4(1453.18,663.08)
WiFi_P05_GPIO_14: J7.1 U3.5 | length 2404.1
  Top Layer w6: v1(551.98,1126.34) 644.21,1126.34 U3.5@646.77,1128.9
  PWR w6: v1(551.98,1126.34) 545.4,1119.76 545.4,1024.93 526.38,1005.9 526.38,978.18 559.36,945.21 559.36,915.64 559.36,711.32 885.17,385.51 885.17,336.73 927.44,294.45 1113.71,294.45 1224.4,183.76 1273.39,183.76 1372.86,283.23 1436.2,283.23 1500.48,347.51 1631.2,347.51 1680.16,396.47 1961.6,396.47 1974.21,383.86 J7.1@2087.92,383.86
WiFi_P06_GPIO_15: J8.1 U3.6 | length 2730.2
  Top Layer w6: v1(612.07,1096.31) 624.97,1109.21 U3.6@646.77,1109.21
  PWR w6: v1(612.07,1096.31) 612.07,695.02 870.36,436.73 870.36,421.68 905.07,386.97 905.07,363.45 927.79,340.73 1093.59,340.73 1229.82,204.51 1277.12,204.51 1366.84,294.23 1427.16,294.23 1517.38,384.45 1599.22,384.45 1853.94,639.17 1853.94,911.55 1932.35,989.97 1932.35,1027.9 J8.1@2087.92,1183.47
WiFi_P16_JTAG_TDI: J1.8 U3.16 | length 1006.6
  Top Layer w6: v1(-150.98,1091.65) J1.8@-88.71,1091.65 ; v1(368.35,855.11) 430.04,855.11 453.61,831.54 562.76,831.54 600,868.78 600,878 634.36,912.36 U3.16@646.77,912.36
  Bottom Layer w6: v1(-150.98,1091.65) 70.17,870.51 352.95,870.51 v1(368.35,855.11)
WiFi_P17_JTAG_TDO: J1.6 U3.17 | length 1032.9
  Top Layer w6: v1(-150.98,1041.65) J1.6@-88.71,1041.65 ; v1(408,832.02) 427.42,832.02 452.68,806.76 586.76,806.76 614,834 614,864 636.77,886.77 U3.17@672.36,886.77
  Bottom Layer w6: v1(-150.98,1041.65) 56.99,833.69 v1@408,833.69
WiFi_P18_GPIO_28: R36.2 U3.18 U5.6 | length 817
  Top Layer w6: v1(645,860) 674.91,860 692.05,877.14 U3.18@692.05,886.77 ; U5.6@975.63,502.41 975.63,486.99 R36.2@990.63,471.99 ; R36.2@994.35,471.99 v1(1015.82,471.99)
  Bottom Layer w6: v1(645,860) 645,668.18 809.5,503.69 865.37,503.69 907.1,545.41 946.81,545.41 974.45,517.77 974.45,489.28 991.75,471.99 v1(1015.82,471.99)
WiFi_P19_JTAG_TCK: J1.4 U3.19 | length 1064.4
  Top Layer w6: v1(-150.98,991.65) J1.4@-88.71,991.65 ; v1(368.35,808.93) 412.5,808.93 429.59,791.84 592.84,791.84 635.21,834.21 667.82,834.21 711.73,878.12 U3.19@711.73,886.77
  Bottom Layer w6: v1(-150.98,991.65) 46.61,794.07 353.49,794.07 v1(368.35,808.93)
WiFi_P20_JTAG_TMS: J1.2 U3.20 | length 1082.9
  Top Layer w6: v1(-150.98,941.65) J1.2@-88.71,941.65 ; v1(408,785.83) 416.76,777.07 600.01,777.07 643.48,820.54 673.78,820.54 731.42,878.18 U3.20@731.42,886.77
  Bottom Layer w6: v1(-150.98,941.65) 25.96,764.72 381.88,764.72 v1@408,790.83
WiFi_P34_SOP1: J10.4 R31.2 U3.34 | length 1961.8
  Top Layer w6: U3.34@993.23,932.05 1006.86,932.05 1014.79,924.12 1014.79,913.82 v1(1028.23,900.39) ; v6(1681.95,1027.73) R31.2@1681.95,1065.54 1834.08,1065.54 J10.4@1884.35,1115.81
  PWR w6: v1(1028.23,900.39) 1028.23,882.53 1056.74,854.02 1056.74,676.12 1080.75,652.1 1080.75,627.61 1123.69,584.67 1123.69,573.04 1167.72,529.01 1167.72,418.32 1240.76,345.29 1402.98,345.29 1456.93,399.24 1456.93,430.29 1492.03,465.38 1565.92,465.38 1681.95,581.4 v6(1681.95,1027.73)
